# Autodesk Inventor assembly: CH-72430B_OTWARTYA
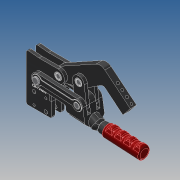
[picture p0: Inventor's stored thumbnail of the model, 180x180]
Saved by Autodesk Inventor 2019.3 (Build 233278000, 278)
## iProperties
Company: Î¢ÈíÖÐ¹ú
Created: 2012-10
Part Number: CH-72430B_OTWARTYA
Material: Ogólny
Description: STEP AP203
Document SubType Name: Assembly
Designer: CADENGINEERING4
Sending System: SolidWorks 2010
Preprocessor: SwSTEP 2.0
Title: CH-72430B.STEP
Author: Î¢ÈíÓÃ»§
Revision Number: ÈÎºÎ
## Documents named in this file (12)
- E:\CAD_CLAMPS\Heavy duty weldables\CH-72430B_DODAC\CH-72430B_OTWARTY.iam
- E:\CAD_CLAMPS\Heavy duty weldables\CH-72430B_DODAC\72425-06.ipt
- E:\CAD_CLAMPS\Heavy duty weldables\CH-72430B_DODAC\CH-72430B-01.ipt
- E:\CAD_CLAMPS\Heavy duty weldables\CH-72430B_DODAC\72425-09.ipt
- E:\CAD_CLAMPS\Heavy duty weldables\CH-72430B_DODAC\72425-04.ipt
- E:\CAD_CLAMPS\Heavy duty weldables\CH-72430B_DODAC\72425-07.ipt
- E:\CAD_CLAMPS\Heavy duty weldables\CH-72430B_DODAC\72425-08.ipt
- E:\CAD_CLAMPS\Heavy duty weldables\CH-72430B_DODAC\M12.ipt
- E:\CAD_CLAMPS\Heavy duty weldables\CH-72430B_DODAC\72425-10.ipt
- E:\CAD_CLAMPS\Heavy duty weldables\CH-72430B_DODAC\72425-11.ipt
- E:\CAD_CLAMPS\Heavy duty weldables\CH-72430B_DODAC\CH-72430B-02.ipt
- E:\CAD_CLAMPS\Heavy duty weldables\CH-72430B_DODAC\72425-03.ipt
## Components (20 placed, 20 different names)
1. 72425-06_1 — Zestawiające:14, Równoległe:3
2. 72425-06_2 — Zestawiające:19, Równoległe:6
3. 72425-06_3 — Zestawiające:21, Równoległe:8, Zestawiające:23, Zestawiające:27
4. CH-72430B-01_4 — Zestawiające:18, Równoległe:5, Zestawiające:19, Równoległe:6, Równoległe:7, Zestawiające:21, Równoległe:8, Zestawiające:22, Równoległe:9, Zestawiające:24, Zestawiające:26, Zestawiające:33
5. 72425-06_5 — Zestawiające:13, Równoległe:2, Zestawiające:15
6. 72425-09_6 — Zestawiające:23, Zestawiające:24
7. 72425-06_7 — Zestawiające:18, Równoległe:5, Zestawiające:20
8. 72425-04_8 — Zestawiające:1, Zestawiające:3, Zestawiające:4, Zestawiające:5, Zestawiające:6, Zestawiające:12, Równoległe:1, Zestawiające:27, Zestawiające:28, Zestawiające:29, Zestawiające:31, Zestawiające:32, Zestawiające:33, Kątowe:1
9. 72425-07_9 — Zestawiające:12, Równoległe:1
10. 72425-06_10 — Zestawiające:8, Zestawiające:9
11. 72425-08_11 — Zestawiające:15, Równoległe:4, Zestawiające:17
12. M12_12 — Zestawiające:30, Zestawiające:31
13. 72425-10_13 — Zestawiające:28, Zestawiające:29, Zestawiające:30
14. 72425-11_14 — Zestawiające:1, Zestawiające:32, Kątowe:1
15. CH-72430B-02_15 — Zestawiające:16, Zestawiające:17, Zestawiające:25, Zestawiające:26
16. 72425-06_16 — Zestawiające:22, Równoległe:9
17. 72425-08_17 — Zestawiające:20, Równoległe:7, Zestawiające:25
18. 72425-03_18 — Zestawiające:3, Zestawiające:4, Zestawiające:7, Zestawiające:10, Zestawiające:11, Zestawiające:13, Równoległe:2, Równoległe:4, Zestawiające:16
19. 72425-03_19 — Zestawiające:5, Zestawiające:6, Zestawiające:7, Zestawiające:8, Zestawiające:9, Zestawiające:14, Równoległe:3
20. 72425-06_20 — Zestawiające:10, Zestawiające:11
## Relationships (42: Mate 32, Flush 9, Angle 1)
- Zestawiające:1 [Mate]: 72425-04_8 ↔ 72425-11_14
- Zestawiające:3 [Mate]: 72425-04_8 ↔ 72425-03_18
- Zestawiające:4 [Mate]: 72425-04_8 ↔ 72425-03_18
- Zestawiające:5 [Mate]: 72425-04_8 ↔ 72425-03_19
- Zestawiające:6 [Mate]: 72425-04_8 ↔ 72425-03_19
- Zestawiające:7 [Mate]: 72425-03_18 ↔ 72425-03_19
- Zestawiające:8 [Mate]: 72425-06_10 ↔ 72425-03_19
- Zestawiające:9 [Mate]: 72425-06_10 ↔ 72425-03_19
- Zestawiające:10 [Mate]: 72425-03_18 ↔ 72425-06_20
- Zestawiające:11 [Mate]: 72425-03_18 ↔ 72425-06_20
- Zestawiające:12 [Mate]: 72425-04_8 ↔ 72425-07_9
- Równoległe:1 [Flush]: 72425-04_8 ↔ 72425-07_9
- Zestawiające:13 [Mate]: 72425-06_5 ↔ 72425-03_18
- Zestawiające:14 [Mate]: 72425-06_1 ↔ 72425-03_19
- Równoległe:2 [Flush]: 72425-06_5 ↔ 72425-03_18
- Równoległe:3 [Flush]: 72425-06_1 ↔ 72425-03_19
- Zestawiające:15 [Mate]: 72425-06_5 ↔ 72425-08_11
- Równoległe:4 [Flush]: 72425-08_11 ↔ 72425-03_18
- Zestawiające:16 [Mate]: CH-72430B-02_15 ↔ 72425-03_18
- Zestawiające:17 [Mate]: 72425-08_11 ↔ CH-72430B-02_15
- Zestawiające:18 [Mate]: CH-72430B-01_4 ↔ 72425-06_7
- Równoległe:5 [Flush]: CH-72430B-01_4 ↔ 72425-06_7
- Zestawiające:19 [Mate]: 72425-06_2 ↔ CH-72430B-01_4
- Równoległe:6 [Flush]: 72425-06_2 ↔ CH-72430B-01_4
- Zestawiające:20 [Mate]: 72425-06_7 ↔ 72425-08_17
- Równoległe:7 [Flush]: CH-72430B-01_4 ↔ 72425-08_17
- Zestawiające:21 [Mate]: 72425-06_3 ↔ CH-72430B-01_4
- Równoległe:8 [Flush]: 72425-06_3 ↔ CH-72430B-01_4
- Zestawiające:22 [Mate]: CH-72430B-01_4 ↔ 72425-06_16
- Równoległe:9 [Flush]: CH-72430B-01_4 ↔ 72425-06_16
- Zestawiające:23 [Mate]: 72425-06_3 ↔ 72425-09_6
- Zestawiające:24 [Mate]: CH-72430B-01_4 ↔ 72425-09_6
- Zestawiające:25 [Mate]: CH-72430B-02_15 ↔ 72425-08_17
- Zestawiające:26 [Mate]: CH-72430B-01_4 ↔ CH-72430B-02_15
- Zestawiające:27 [Mate]: 72425-06_3 ↔ 72425-04_8
- Zestawiające:28 [Mate]: 72425-04_8 ↔ 72425-10_13
- Zestawiające:29 [Mate]: 72425-04_8 ↔ 72425-10_13
- Zestawiające:30 [Mate]: M12_12 ↔ 72425-10_13
- Zestawiające:31 [Mate]: 72425-04_8 ↔ M12_12
- Zestawiające:32 [Mate]: 72425-04_8 ↔ 72425-11_14
- Zestawiające:33 [Mate]: CH-72430B-01_4 ↔ 72425-04_8
- Kątowe:1 [Angle]: 72425-04_8 ↔ 72425-11_14
